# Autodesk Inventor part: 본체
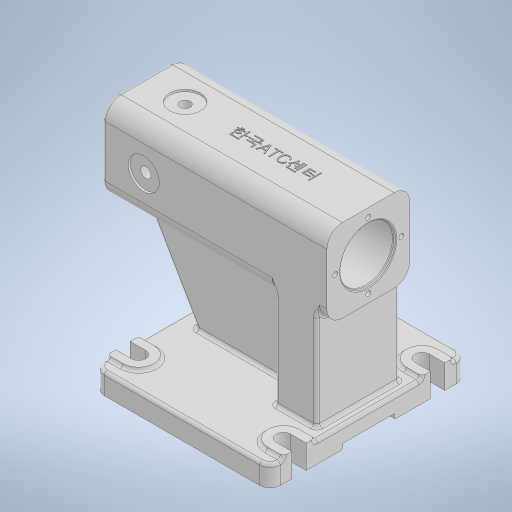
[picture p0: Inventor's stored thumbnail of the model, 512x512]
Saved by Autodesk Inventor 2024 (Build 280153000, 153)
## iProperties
Created: 2024-08
Part Number: 본체
Material: 알루미늄 6061
Document SubType Name: Modeling
Designer: user
Density: 2.7 g/cm^3
Appearance: 알루미늄 - 평지
Mass: 5666.24 g
Surface Area: 2208.06 cm^2
Volume: 2098.61 cm^3
Sending System: Autodesk Inventor 2025
Preprocessor: ST-DEVELOPER v20
Author: jhkim
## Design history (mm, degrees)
feature "솔리드1"
node "솔리드2"
